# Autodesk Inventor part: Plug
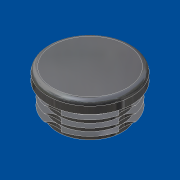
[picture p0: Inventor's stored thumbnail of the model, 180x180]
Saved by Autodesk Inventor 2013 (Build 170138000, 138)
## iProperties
Shininess: 69.0
Length Units: 11269
Angle Units: 11279
Time Units: 11290
Mass Units: 11283
Length Display Precision: 3
Angle Display Precision: 2
Created: 2001-04
Part Number: Plug
Material: Standard
Document SubType Name: Modellieren
Designer: dl
Density: 1 g/cm^3
Density: 0.0
Volumn: 0.0
Area: 0.0
PropertySet Name: Model Information
Control State: 0
Master: False
Checked Out: False
Author: dl
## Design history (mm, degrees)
body "Solid1"
sketch "Sketch2"
  geometry: C1 r 13.5 at (0, 0) reference; 1 further point
  constraints: 1 coincident
sketch "Sketch3"
  geometry: C1 r 4 at (0, 17.5); C2 r 17.5 at (0, 0) reference
  constraints: 1 centre point
  dimensions: "d21" = 8 diameter of C1; "d22" = 17.5 distance of C2.centre C1.centre; "d23" = 0 horizontal distance of C2.centre C1.centre
revolve "Revolution1" stored, may be unused: angle "d11" = 90 deg
hole "Hole1" sketch "Sketch2" diameter "d12" = 25; stored, may be unused: countersink angle "d16" = 60 deg, drill point angle "d18" = 0 deg; dims "d13" = 6, "d14" = 4, "d15" = 2, "d17" = 15
fillet "Fillet1" dims "d19" = 2
fillet "Fillet2" dims "d20" = 2
extrude "Extrusion1" cut sketch "Sketch3" stored distance "d24" = 10; taper "d25" = 0 deg
pattern_circular "Circular Pattern1" dims angle "d28" = 360 deg
sketch "Sketch1"
  geometry: L1 (0, 18.864)-(0, 35.864); L2 (0, 35.864)-(17.5, 35.864); L3 (17.5, 35.864)-(17.5, 30.864); L4 (17.5, 30.864)-(13.5, 30.864); L5 (13.5, 30.864)-(13.5, 27.864); L6 (13.5, 27.864)-(16, 27.864); L7 (16, 27.864)-(13.5, 26.421); L8 (13.5, 26.421)-(13.5, 24.864); L9 (13.5, 24.864)-(16, 24.864); L10 (16, 24.864)-(13.5, 23.421); L11 (13.5, 23.421)-(13.5, 21.864); L12 (13.5, 21.864)-(16, 21.864); L13 (16, 21.864)-(13.5, 20.421); L14 (13.5, 20.421)-(13.5, 18.864); L15 (13.5, 18.864)-(0, 18.864)
  constraints: 30 end point, 13 parallel, 3 collinear, 1 perpendicular, 1 vertical
  dimensions: "d0" = 17.5 distance of L1.end L2.end; "d1" = 30 deg angle of L7 L6; "d2" = 13.5 distance between parallel lines of L1 L14; "d3" = 16 distance from line of L1 L12.end; "d4" = 16 horizontal distance of L1.end L6.end (= d3); "d5" = 16 horizontal distance of L1.end L9.end (= d3); "d6" = 5 distance of L2.end L3.end; "d7" = 3 distance of L4.end L5.end; "d8" = 3 distance between parallel lines of L6 L9; "d9" = 3 distance between parallel lines of L12 L9 (= d8); "d10" = 17 distance of L1.start L1.end
